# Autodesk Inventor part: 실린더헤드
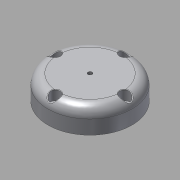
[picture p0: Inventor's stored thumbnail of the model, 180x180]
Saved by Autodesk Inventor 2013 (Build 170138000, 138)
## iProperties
Created: 2016-11
Part Number: 실린더헤드
Material: 알루미늄 6061
Document SubType Name: Modeling
Designer: mduedu
Density: 2.71 g/cm^3
Mass: 258.244 g
Surface Area: 216.959 cm^2
Volume: 95.2929 cm^3
Author: mduedu
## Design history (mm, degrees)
sketch "스케치1"
  geometry: C1 r 42 at (0, 0); 1 further point
  constraints: 1 centre point, 1 coincident
  dimensions: "d0" = 84 diameter of C1
extrude "돌출1" new body sketch "스케치1" distance "d1" = 24; taper "d2" = 0 deg
fillet "모깎기1" dims "d3" = 10
sketch "스케치2"
  geometry: C1 r 30 at (0, 0); 1 further point
  constraints: 1 centre point, 1 coincident
  dimensions: "d4" = 60 diameter of C1
extrude "돌출2" join sketch "스케치2" distance "d5" = 5; taper "d6" = 0 deg
sketch "스케치3"
  geometry: C1 r 25 at (0, 0); 1 further point
  constraints: 1 centre point, 1 coincident
  dimensions: "d7" = 50 diameter of C1
extrude "돌출3" cut sketch "스케치3" distance "d8" = 20; taper "d9" = 0 deg
hole "구멍1" diameter "d12" = 4.134; stored, may be unused: countersink angle "d16" = 90 deg, drill point angle "d18" = 118 deg; dims "d10" = 10, "d11" = 10, "d13" = 6, "d14" = 4, "d15" = 2, "d17" = 8
chamfer "모따기1" distance "d19" = 1; stored, may be unused: second distance "d20" = 2, angle "d21" = 45 deg
fillet "모깎기2" dims "d22" = 3
sketch "스케치4"
  geometry: C1 r 17.5 at (0, 0); 1 further point
  constraints: 1 centre point, 1 coincident
  dimensions: "d23" = 35 diameter of C1
extrude "돌출4" cut sketch "스케치4" distance "d24" = 2; taper "d25" = 0 deg
fillet "모깎기3" dims "d26" = 0.5
sketch "스케치5" dims "d32" = 70
  geometry: C1 r 5 at (0, 35); 3 further points
  constraints: 2 coincident, 2 vertical alignment, 1 centre point, 2 other
  dimensions: "d33" = 10 diameter of C1
extrude "돌출5" cut sketch "스케치5" distance "d34" = 10; taper "d35" = 0 deg
sketch "스케치6" dims "d39" = 70
  geometry: 6 further points
  constraints: 2 vertical alignment, 1 coincident, 7 other
  dimensions: "d42" = 360 deg dimension on point (0, -35) point (0, 0) (derived)
sketch "스케치7"
  geometry: 4 further points
  constraints: 4 other
hole "구멍2" sketch "스케치7" at (0, 70), (-35, 35), (35, 35), (0, 0) diameter "d44" = 5.5; stored, may be unused: countersink angle "d48" = 90 deg, drill point angle "d50" = 0 deg; dims "d45" = 6, "d46" = 4, "d47" = 2, "d49" = 8
fillet "모깎기4" dims "d51" = 0.5
chamfer "모따기2" distance "d54" = 5; stored, may be unused: second distance "d55" = 2, angle "d56" = 30 deg
node "솔리드1"
pattern_circular "원형 패턴1" dims angle "d37" = 360 deg
